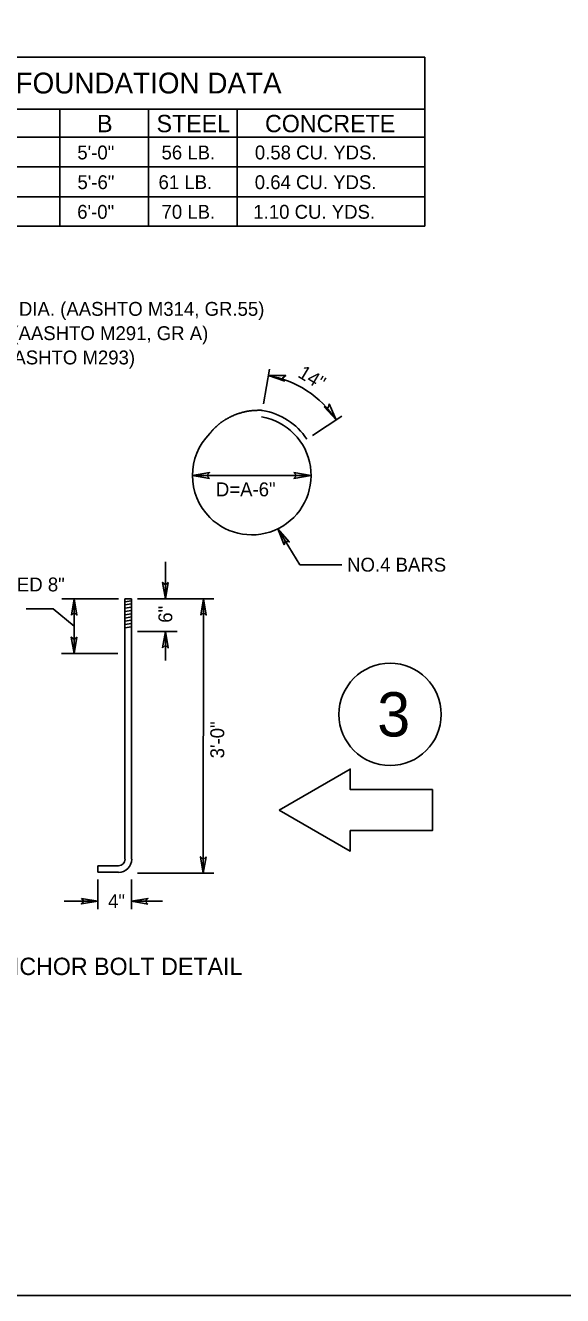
# Model space of a CAD drawing. Extents: x 99836 to 115004, y 99786 to 102182.
# Drawn here: x 101048 to 101512, y 99886 to 100984 of the extents above; entities that cross this region are included whole.
import ezdxf

# ---------------------------------------------------------------- set-up
doc = ezdxf.new("R2010")
doc.units = 0
for name, color, linetype in [('Border Organizer Shape', 7, 'Continuous'), ('Default', 7, 'Continuous'), ('Notes General Notes', 7, 'Continuous')]:
    doc.layers.add(name, color=color, linetype=linetype)

msp = doc.modelspace()

# ---------------------------------------------------------------- linework, layer by layer
at = {"layer": 'Border Organizer Shape'}
for p, q in [((100776.4, 100956.7), (101393.2, 100956.7)), ((101393.2, 100810.4), (101393.2, 100956.7)), ((100776.4, 100911.7), (101393.2, 100911.7)), ((101077.6, 100810.4), (101077.6, 100911.7)), ((101154.3, 100810.4), (101154.3, 100911.7)), ((101230.9, 100810.4), (101230.9, 100911.7)), ((100776.4, 100887.4), (101393.2, 100887.4)), ((100776.4, 100861.7), (101393.2, 100861.7)), ((100776.4, 100836), (101393.2, 100836)), ((100776.4, 100810.4), (101393.2, 100810.4)), ((101253.8, 100657), (101258.8, 100686.9)), ((101296, 100629.7), (101321.4, 100646.4)), ((101192.2, 100595), (101294.8, 100595)), ((101168.8, 100488.5), (101168.9, 100520.4)), ((101128.4, 100488.5), (101079.2, 100488.5)), ((101089.9, 100441.2), (101090, 100488.5)), ((101133.9, 100488.5), (101133.9, 100469.6)), ((101139.6, 100488.5), (101133.9, 100488.5)), ((101139.6, 100486.7), (101133.9, 100485.8)), ((101139.6, 100484), (101133.9, 100483.1)), ((101139.6, 100481.2), (101133.9, 100480.3)), ((101139.6, 100488.5), (101139.6, 100469.6)), ((101210.7, 100488.4), (101144.8, 100488.5)), ((101201.6, 100251.3), (101201.8, 100488.5)), ((101071.7, 100479.7), (101048.4, 100479.8)), ((101071.7, 100479.7), (101089.9, 100464.8)), ((101139.5, 100478.4), (101133.9, 100477.5)), ((101139.5, 100475.4), (101133.9, 100474.5)), ((101139.5, 100472.7), (101133.9, 100471.8)), ((101139.5, 100469.9), (101133.9, 100469)), ((101133.9, 100469.6), (101133.9, 100263.3)), ((101139.5, 100467.1), (101133.9, 100466.2)), ((101139.5, 100464.1), (101133.9, 100463.2)), ((101139.6, 100469.6), (101139.6, 100263.3)), ((101178.9, 100460.1), (101144.8, 100460.1)), ((101168.8, 100435.1), (101168.8, 100460.1)), ((101127.8, 100441.2), (101079.1, 100441.2)), ((101110.3, 100257.7), (101128.3, 100257.7)), ((101110.3, 100257.7), (101110.3, 100252)), ((101110.3, 100252), (101128.3, 100252)), ((101210.6, 100251.3), (101144.6, 100251.3)), ((101110.3, 100220.1), (101110.3, 100245.8)), ((101139.6, 100220.1), (101139.6, 100245.8)), ((101110.3, 100227.1), (101081.3, 100227.1)), ((101166.3, 100227), (101139.6, 100227.1))]:
    msp.add_line(p, q, dxfattribs=at)
for points in [[(101272.1, 100676.4), (101257.9, 100681.3), (101272.9, 100681.3), (101270.2, 100679.2)], [(101310.4, 100657), (101316.5, 100643.2), (101306.2, 100654.2), (101309.6, 100653.6)], [(101207.1, 100592.5), (101192.2, 100595), (101207.1, 100597.5), (101204.7, 100595)], [(101280, 100597.5), (101294.8, 100595), (101280, 100592.5), (101282.3, 100595)], [(101271.6, 100535), (101266, 100548.9), (101275.9, 100537.6), (101272.5, 100538.3)], [(101171.2, 100502.6), (101168.8, 100488.5), (101166.4, 100502.6), (101168.8, 100500.4)], [(101087.6, 100474.4), (101090, 100488.5), (101092.3, 100474.4), (101089.9, 100476.6)], [(101199.4, 100474.4), (101201.8, 100488.5), (101204.2, 100474.3), (101201.8, 100476.6)], [(101166.4, 100446), (101168.8, 100460.1), (101171.2, 100446), (101168.8, 100448.2)], [(101092.3, 100455.3), (101089.9, 100441.2), (101087.5, 100455.3), (101089.9, 100453.1)], [(101204, 100265.4), (101201.6, 100251.3), (101199.2, 100265.4), (101201.6, 100263.1)], [(101096.2, 100229.5), (101110.3, 100227.1), (101096.2, 100224.7), (101098.4, 100227.1)], [(101153.7, 100224.6), (101139.6, 100227.1), (101153.7, 100229.4), (101151.5, 100227)]]:
    msp.add_lwpolyline(points, close=True, dxfattribs=at)
msp.add_lwpolyline([(101266, 100548.9), (101285.1, 100517.9), (101321.5, 100517.9)], dxfattribs=at)
for centre, radius, start, end in [((101243.5, 100595), 87.4, 33.427, 80.5536), ((101243.5, 100595), 57, 33.4279, 80.5568), ((101243.5, 100595), 51.3, 224.9925, 80.5568), ((101243.5, 100595), 51.3, 134.9925, 224.9925), ((101128.3, 100263.3), 5.68, 270, 360), ((101128.3, 100263.3), 11.4, 270, 360)]:
    msp.add_arc(centre, radius, start, end, dxfattribs=at)
msp.add_spline([(101252.9, 100651.3), (101252.1, 100651.3), (101251.3, 100651.4), (101250.5, 100651.4), (101249.7, 100651.4), (101249, 100651.4), (101248.1, 100651.3), (101247.3, 100651.3), (101246.5, 100651.3), (101245.8, 100651.2), (101244.9, 100651.1), (101244.1, 100651.1), (101243.3, 100651), (101242.6, 100650.9), (101241.7, 100650.8), (101241, 100650.7), (101240.2, 100650.6), (101239.5, 100650.5), (101238.6, 100650.3), (101237.8, 100650.1), (101237.1, 100649.9), (101236.3, 100649.7), (101235.5, 100649.6), (101234.8, 100649.4), (101234, 100649.1), (101233.3, 100648.9), (101232.4, 100648.7), (101231.7, 100648.5), (101231, 100648.2), (101230.3, 100647.9), (101229.4, 100647.6), (101228.7, 100647.3), (101228, 100647), (101227.2, 100646.7), (101226.5, 100646.4), (101225.8, 100646), (101225.1, 100645.6), (101224.4, 100645.3), (101223.7, 100644.9), (101223, 100644.5), (101222.3, 100644.2), (101221.6, 100643.8), (101220.9, 100643.4), (101220.2, 100643), (101219.6, 100642.5), (101218.9, 100642.1), (101218.2, 100641.6), (101217.6, 100641.2), (101216.9, 100640.7), (101216.3, 100640.3), (101215.7, 100639.7), (101215.1, 100639.3), (101214.5, 100638.7), (101213.8, 100638.3), (101213.3, 100637.7), (101212.7, 100637.2), (101212.1, 100636.6), (101211.6, 100636.1), (101211, 100635.5), (101210.4, 100634.9), (101209.8, 100634.3), (101209.4, 100633.8), (101208.8, 100633.1), (101208.3, 100632.5), (101207.7, 100632), (101207.3, 100631.3)], degree=3, dxfattribs=at)
at = {"layer": 'Default'}
msp.add_lwpolyline([(99976.3, 102085.7), (103176, 102085.7), (103176, 99886.1), (99976.3, 99886.1)], close=True, dxfattribs=at)
at = {"layer": 'Notes General Notes'}
msp.add_lwpolyline([(101267.3, 100305.8), (101328.7, 100270.3), (101328.7, 100288), (101399.7, 100288), (101399.7, 100323.5), (101328.7, 100323.5), (101328.7, 100341.2)], close=True, dxfattribs=at)
msp.add_circle((101363.1, 100388.5), 44.2, dxfattribs=at)

# ---------------------------------------------------------------- texts
at = {"layer": 'Border Organizer Shape'}
for s, height, p in [('STREET LIGHT FOUNDATION DATA', 18, (100860.1, 100925.2)), ('B', 15, (101109.8, 100891.7)), ('STEEL', 15, (101161.2, 100891.7)), ('CONCRETE', 15, (101255, 100891.7)), ('5\'-0"', 12, (101092.7, 100868.2)), ('56 LB.', 12, (101165.5, 100868.2)), ('0.58 CU. YDS.', 12, (101246.2, 100868.2)), ('5\'-6"', 12, (101092.8, 100842.5)), ('61 LB.', 12, (101162.9, 100842.5)), ('0.64 CU. YDS.', 12, (101246.1, 100842.5)), ('6\'-0"', 12, (101092.6, 100816.9)), ('70 LB.', 12, (101165.5, 100816.9)), ('1.10 CU. YDS.', 12, (101244.9, 100816.9)), ('ANCHOR BOLTS GALVANIZED: 1" DIA. (AASHTO M314, GR.55)', 12, (100781.5, 100733)), ('HEAVY HEX GALVANIZED NUTS: (AASHTO M291, GR A)', 12, (100781.5, 100712)), ('FLAT WASHERS GALVANIZED: (AASHTO M293)', 12, (100781.5, 100691)), ('GALVANIZED 8"', 12, (100961.1, 100494.8)), ('4"', 12, (101119.3, 100221.1)), ('ANCHOR BOLT DETAIL', 15, (101014.7, 100163.2))]:
    msp.add_text(s, height=height, dxfattribs=at).set_placement(p)
for s, rotation, p in [('14"', 328.8322, (101282.5, 100680.6)), ('D=A-6"', 359.9925, (101212.5, 100577)), (' NO.4 BARS', 359.9925, (101321.5, 100511.9)), ('6"', 90, (101174.8, 100467.7)), ('3\'-0"', 90, (101219.7, 100350.5))]:
    msp.add_text(s, height=12, rotation=rotation, dxfattribs=at).set_placement(p)
at = {"layer": 'Notes General Notes'}
msp.add_text('3', height=38.3, dxfattribs=at).set_placement((101352, 100369.4))

doc.saveas('drawing.dxf')
